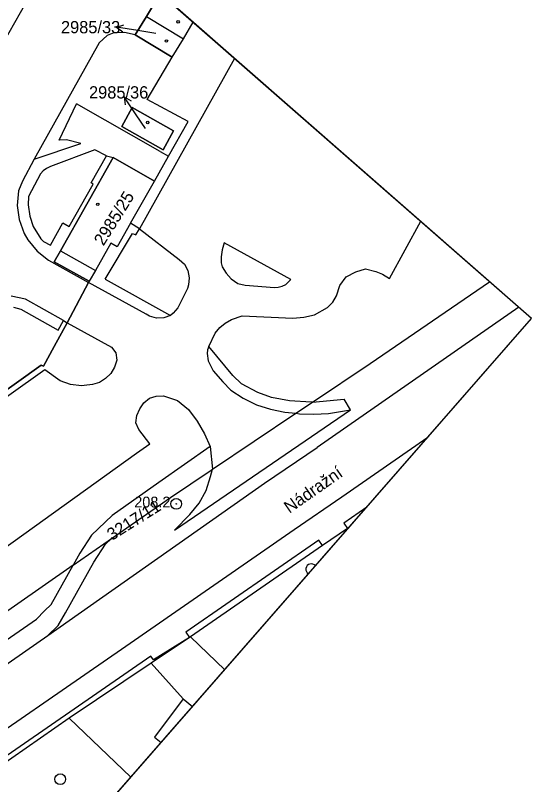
# Model space of a CAD drawing. Extents: x -620475 to -619963, y -1123010 to -1122510.
# Drawn here: x -620034.5 to -619962.9, y -1122851.2 to -1122744.6 of the extents above; entities that cross this region are included whole.
import ezdxf

# ---------------------------------------------------------------- set-up
doc = ezdxf.new("R2010")
doc.units = 0
for name, color, linetype in [('Hranice parcel', 7, 'Continuous'), ('Parcelní čísla', 7, 'Continuous'), ('Pop  PČ popisy', 7, 'Continuous'), ('Rámečky', 7, 'Continuous'), ('Rámečky-tisk', 7, 'Continuous'), ('Vnitřní kresba', 7, 'Continuous'), ('Věcná břemena k části', 7, 'Continuous'), ('Značky bodu BP', 7, 'Continuous'), ('Značky budov', 7, 'Continuous'), ('Značky kultur', 7, 'Continuous')]:
    doc.layers.add(name, color=color, linetype=linetype)

msp = doc.modelspace()

# ---------------------------------------------------------------- linework, layer by layer
at = {"layer": 'Hranice parcel'}
for p, q in [((-620014.82, -1122742.21), (-620016.36, -1122744.78)), ((-620016.36, -1122744.78), (-620011.23, -1122747.87)), ((-620011.23, -1122747.87), (-620009.85, -1122745.57)), ((-620012.77, -1122750.41), (-620011.23, -1122747.87)), ((-620018.54, -1122773.42), (-620015.21, -1122767.58)), ((-620007.52, -1122804.34), (-620007.17, -1122807.47)), ((-620026.52, -1122820.79), (-620021.18, -1122817.07)), ((-620010.26, -1122830.7), (-620005.5, -1122835.25)), ((-620015.7, -1122834.36), (-620027.05, -1122841.96)), ((-620027.05, -1122841.96), (-620041.07, -1122851.68)), ((-620027.05, -1122841.96), (-620018.53, -1122850.14))]:
    msp.add_line(p, q, dxfattribs=at)
for points in [[(-620027.34, -1122787.19), (-620029.12, -1122790.47), (-620030.63, -1122793.23), (-620030.93, -1122793.08), (-620062.93, -1122815.9), (-620079.47, -1122827.69), (-620107.97, -1122811.15), (-620126.88, -1122800.18), (-620134.93, -1122794.41), (-620148.77, -1122775.1), (-620158.3, -1122761.8), (-620160.13, -1122754.62), (-620158.82, -1122744.94), (-620155.87, -1122738.11), (-620144.37, -1122714.62)], [(-620016.36, -1122744.78), (-620017.89, -1122747.34), (-620012.77, -1122750.41)], [(-620004.12, -1122750.58), (-620017.33, -1122774.17), (-620018.54, -1122773.42)], [(-620015.21, -1122767.58), (-620013.28, -1122764.14), (-620010.56, -1122759.32), (-620016.25, -1122756.27), (-620012.77, -1122750.41)], [(-620019.78, -1122760.01), (-620014.04, -1122763.25), (-620012.58, -1122760.64), (-620018.31, -1122757.41), (-620019.78, -1122760.01)], [(-620015.21, -1122767.58), (-620020.97, -1122764.3), (-620028.26, -1122777.23), (-620029.12, -1122778.75), (-620024.29, -1122781.46)], [(-620018.54, -1122773.42), (-620020.4, -1122776.68), (-620021.28, -1122776.18), (-620023.43, -1122779.95), (-620024.29, -1122781.46)], [(-619993.34, -1122798.19), (-619993.51, -1122798.21), (-619996.52, -1122797.99), (-619999.01, -1122797.54), (-620000.91, -1122796.86), (-620003.16, -1122795.65), (-620004.39, -1122794.52), (-620007.71, -1122790.48), (-620006.81, -1122788.65), (-620006.19, -1122787.87), (-620005.43, -1122787.26), (-620004.57, -1122786.74), (-620003.06, -1122786.26), (-619996.05, -1122786.56), (-619994.54, -1122786.44), (-619993.04, -1122786.08), (-619991.26, -1122785.1), (-619990.52, -1122784.36), (-619990, -1122783.48), (-619989.53, -1122782.06), (-619988.65, -1122780.83), (-619987.32, -1122780.16), (-619985.99, -1122779.75), (-619984.54, -1122780.1), (-619983.61, -1122780.49), (-619982.64, -1122781.05), (-619978.32, -1122773.15)], [(-620024.29, -1122781.46), (-620024.38, -1122781.64), (-620027.34, -1122787.19)], [(-619993.34, -1122798.19), (-619985.33, -1122792.82), (-619968.77, -1122781.51)], [(-620027.34, -1122787.19), (-620021.21, -1122790.6), (-620020.57, -1122791.37), (-620020.47, -1122792.38), (-620020.76, -1122793.34), (-620021.28, -1122794.22), (-620022.02, -1122794.92), (-620022.87, -1122795.46), (-620023.84, -1122795.75), (-620024.96, -1122795.87), (-620025.37, -1122795.91), (-620026.87, -1122795.75), (-620028.3, -1122795.22), (-620030.44, -1122793.73), (-620056.1, -1122811.95)], [(-620043.43, -1122823.66), (-620017.73, -1122805.26), (-620015.89, -1122803.95), (-620017.39, -1122801.99), (-620017.8, -1122801.06), (-620017.7, -1122800.06), (-620017.25, -1122799.14), (-620016.69, -1122798.31), (-620015.92, -1122797.65), (-620014.98, -1122797.35), (-620013.97, -1122797.33), (-620012.05, -1122797.95), (-620010.5, -1122799.22), (-620009.31, -1122800.82), (-620008.3, -1122802.58), (-620007.52, -1122804.34)], [(-620007.17, -1122807.47), (-619995.65, -1122799.74), (-619993.34, -1122798.19)], [(-619977.35, -1122803.07), (-619989.26, -1122811.36), (-619995.85, -1122815.89), (-620011.68, -1122826.8), (-620019.22, -1122832.01), (-620044.54, -1122849.47), (-620064.79, -1122863.44), (-620079.86, -1122873.87), (-620081.95, -1122879.05), (-620081.71, -1122879.39)], [(-620007.52, -1122804.34), (-620014.61, -1122809.32), (-620021.11, -1122813.89), (-620023.96, -1122816.62), (-620025.58, -1122819.12), (-620026.52, -1122820.79)], [(-620021.18, -1122817.07), (-620013.01, -1122811.39), (-620007.39, -1122807.62), (-620007.17, -1122807.47)], [(-619988.22, -1122815.49), (-619988.48, -1122815.67), (-619991.93, -1122818.06), (-620010.26, -1122830.7)], [(-620074.02, -1122848.16), (-620069.41, -1122850.86), (-620061.9, -1122850.43), (-620053.99, -1122846.97), (-620049.77, -1122844.23), (-620030.04, -1122830.5), (-620028.57, -1122829.11), (-620027.57, -1122827.35), (-620023.65, -1122820.37), (-620022.03, -1122817.87), (-620021.18, -1122817.07)], [(-620026.52, -1122820.79), (-620038.5, -1122829.12), (-620047.37, -1122835.25), (-620060.13, -1122844.05), (-620068.97, -1122845.62), (-620069.79, -1122845.77)], [(-620010.26, -1122830.7), (-620010.39, -1122830.79), (-620015.7, -1122834.36)], [(-620015.7, -1122834.36), (-620011.24, -1122839.29), (-620015.25, -1122844.59), (-620014.33, -1122845.34)]]:
    msp.add_lwpolyline(points, dxfattribs=at)
at = {"layer": 'Pop  PČ popisy'}
for p, q in [((-620020.52, -1122746.27), (-620019.46, -1122745.93)), ((-620017.56, -1122746.74), (-620020.52, -1122746.27)), ((-620020.52, -1122746.27), (-620019.61, -1122746.92)), ((-620015.05, -1122747.14), (-620017.56, -1122746.74)), ((-620017.77, -1122758.39), (-620019.45, -1122755.9)), ((-620019.45, -1122755.9), (-620018.47, -1122756.45)), ((-620019.45, -1122755.9), (-620019.3, -1122757.01)), ((-620016.47, -1122760.3), (-620017.77, -1122758.39))]:
    msp.add_line(p, q, dxfattribs=at)
at = {"layer": 'Rámečky'}
for p, q in [((-619962.95, -1122786.6), (-620279.07, -1122510.07)), ((-620158.49, -1123010.14), (-619962.95, -1122786.6))]:
    msp.add_line(p, q, dxfattribs=at)
at = {"layer": 'Rámečky-tisk'}
msp.add_lwpolyline([(-620158.49, -1123010.14), (-619962.95, -1122786.6), (-620279.07, -1122510.07)], dxfattribs=at)
at = {"layer": 'Vnitřní kresba'}
for p, q in [((-620041.55, -1122757.64), (-620033.04, -1122742.83)), ((-620021.79, -1122747.41), (-620022.92, -1122748.42)), ((-620020.88, -1122747.04), (-620021.79, -1122747.41)), ((-620019.38, -1122747), (-620020.88, -1122747.04)), ((-620017.89, -1122747.34), (-620019.38, -1122747)), ((-620022.92, -1122748.42), (-620031.91, -1122764.55)), ((-620028.43, -1122761.89), (-620026.05, -1122756.86)), ((-620014.44, -1122763.48), (-620026.05, -1122756.86)), ((-620027.41, -1122761.88), (-620028.43, -1122761.89)), ((-620025.43, -1122762.36), (-620027.41, -1122761.88)), ((-620031.91, -1122764.55), (-620025.43, -1122762.36)), ((-620023.51, -1122763.25), (-620029.67, -1122765.56)), ((-620021.87, -1122764.08), (-620023.51, -1122763.25)), ((-620024.01, -1122767.82), (-620021.87, -1122764.08)), ((-620021.87, -1122764.08), (-620020.97, -1122764.3)), ((-620014.44, -1122763.48), (-620013.28, -1122764.14)), ((-620031.91, -1122764.55), (-620033.55, -1122767.57)), ((-620031.05, -1122766.59), (-620032.68, -1122769.69)), ((-620030.66, -1122766.18), (-620031.05, -1122766.59)), ((-620030.22, -1122765.84), (-620030.66, -1122766.18)), ((-620029.67, -1122765.56), (-620030.22, -1122765.84)), ((-620033.55, -1122767.57), (-620034.07, -1122768.94)), ((-620027.07, -1122773.88), (-620023.72, -1122768.01)), ((-620023.72, -1122768.01), (-620024.01, -1122767.82)), ((-620034.07, -1122768.94), (-620034.29, -1122770.95)), ((-620032.68, -1122769.69), (-620032.73, -1122770.86)), ((-620032.73, -1122770.86), (-620032.52, -1122772.45)), ((-620034.29, -1122770.95), (-620033.98, -1122772.91)), ((-620033.98, -1122772.91), (-620033.32, -1122774.85)), ((-620032.52, -1122772.45), (-620032.06, -1122773.89)), ((-620032.06, -1122773.89), (-620030.97, -1122775.57)), ((-620029.65, -1122776.45), (-620027.94, -1122773.37)), ((-620027.94, -1122773.37), (-620027.07, -1122773.88)), ((-620033.32, -1122774.85), (-620032.78, -1122775.71)), ((-620022.06, -1122781.16), (-620018.29, -1122774.82)), ((-620018.29, -1122774.82), (-620017.82, -1122775.04)), ((-620017.82, -1122775.04), (-620017.33, -1122774.17)), ((-620017.33, -1122774.17), (-620011.79, -1122778.42)), ((-620032.78, -1122775.71), (-620031.51, -1122777.29)), ((-620030.97, -1122775.57), (-620030.6, -1122775.96)), ((-620030.6, -1122775.96), (-620029.65, -1122776.45)), ((-620005.57, -1122776.13), (-620005.85, -1122777.08)), ((-619996.33, -1122781.23), (-620005.57, -1122776.13)), ((-620028.26, -1122777.23), (-620023.43, -1122779.95)), ((-620005.85, -1122777.08), (-620006.01, -1122778.08)), ((-620031.51, -1122777.29), (-620029.92, -1122778.54)), ((-620006.01, -1122778.08), (-620005.98, -1122778.9)), ((-620029.92, -1122778.54), (-620024.38, -1122781.64)), ((-620011.79, -1122778.42), (-620011.09, -1122779.1)), ((-620011.09, -1122779.1), (-620010.6, -1122779.97)), ((-620005.98, -1122778.9), (-620005.86, -1122779.45)), ((-620010.6, -1122779.97), (-620010.42, -1122780.98)), ((-620005.86, -1122779.45), (-620005.28, -1122780.34)), ((-620005.28, -1122780.34), (-620004.59, -1122781.12)), ((-620022.06, -1122781.16), (-620013.03, -1122786.2)), ((-620010.42, -1122780.98), (-620010.5, -1122781.96)), ((-620004.59, -1122781.12), (-620003.7, -1122781.74)), ((-619997.02, -1122781.9), (-619996.33, -1122781.23)), ((-620016.38, -1122786.03), (-620024.38, -1122781.64)), ((-620010.64, -1122782.44), (-620011.99, -1122785.12)), ((-620010.5, -1122781.96), (-620010.64, -1122782.44)), ((-620003.7, -1122781.74), (-620002.66, -1122782)), ((-620002.66, -1122782), (-619998.58, -1122782.3)), ((-619998.58, -1122782.3), (-619998.07, -1122782.26)), ((-619998.07, -1122782.26), (-619997.52, -1122782.12)), ((-619997.52, -1122782.12), (-619997.02, -1122781.9)), ((-620033.11, -1122783.92), (-620035.08, -1122783.5)), ((-620027.85, -1122786.88), (-620033.11, -1122783.92)), ((-620034.76, -1122785.06), (-620033.77, -1122785.31)), ((-620033.77, -1122785.31), (-620028.59, -1122788.23)), ((-620011.99, -1122785.12), (-620012.63, -1122785.89)), ((-619964.74, -1122785.03), (-619992.67, -1122804.48)), ((-620015.91, -1122786.27), (-620016.38, -1122786.03)), ((-620014.97, -1122786.55), (-620015.91, -1122786.27)), ((-620013.96, -1122786.51), (-620014.97, -1122786.55)), ((-620013.03, -1122786.2), (-620013.96, -1122786.51)), ((-620012.63, -1122785.89), (-620013.03, -1122786.2)), ((-620028.59, -1122788.23), (-620027.85, -1122786.88)), ((-620027.85, -1122786.88), (-620027.34, -1122787.19)), ((-620007.9, -1122790.93), (-620007.92, -1122791.46)), ((-620007.71, -1122790.48), (-620007.9, -1122790.93)), ((-620007.92, -1122791.46), (-620007.77, -1122792.46)), ((-620007.77, -1122792.46), (-620007.09, -1122793.84)), ((-620007.09, -1122793.84), (-620005.78, -1122795.39)), ((-620005.78, -1122795.39), (-620004.64, -1122796.54)), ((-620004.64, -1122796.54), (-620002.93, -1122797.66)), ((-620002.93, -1122797.66), (-620001.11, -1122798.55)), ((-620001.11, -1122798.55), (-619999.17, -1122799.18)), ((-619993.34, -1122798.19), (-619988.95, -1122797.79)), ((-619988.07, -1122799.25), (-619988.95, -1122797.79)), ((-620012.45, -1122815.92), (-619988.07, -1122799.25)), ((-619999.17, -1122799.18), (-619997.16, -1122799.6)), ((-619997.16, -1122799.6), (-619995.65, -1122799.74)), ((-619991.09, -1122799.77), (-619988.07, -1122799.25)), ((-619995.65, -1122799.74), (-619995.15, -1122799.79)), ((-619995.15, -1122799.79), (-619993.12, -1122799.86)), ((-619993.12, -1122799.86), (-619991.09, -1122799.77)), ((-620000, -1122809.41), (-619992.67, -1122804.48)), ((-620007.48, -1122808.49), (-620007.17, -1122807.47)), ((-620008.06, -1122810.42), (-620007.48, -1122808.49)), ((-620030.04, -1122830.5), (-620000, -1122809.41)), ((-620009.06, -1122812.19), (-620008.06, -1122810.42)), ((-620010.31, -1122813.76), (-620009.06, -1122812.19)), ((-619985.8, -1122812.72), (-619988.99, -1122814.93)), ((-620012.45, -1122815.92), (-620010.31, -1122813.76)), ((-619988.99, -1122814.93), (-619988.48, -1122815.67)), ((-619992.45, -1122817.31), (-620010.9, -1122830.03)), ((-619991.93, -1122818.06), (-619992.45, -1122817.31)), ((-620029.57, -1122826.21), (-620026.52, -1122820.79)), ((-620030.46, -1122827.11), (-620029.57, -1122826.21)), ((-620031.61, -1122828.24), (-620030.46, -1122827.11)), ((-620051.34, -1122841.97), (-620031.61, -1122828.24)), ((-620010.9, -1122830.03), (-620010.39, -1122830.79)), ((-620010.39, -1122830.79), (-620015.39, -1122833.86)), ((-620015.73, -1122833.37), (-620081.95, -1122879.05)), ((-620015.39, -1122833.86), (-620015.73, -1122833.37)), ((-620011.24, -1122839.29), (-620009.96, -1122840.34))]:
    msp.add_line(p, q, dxfattribs=at)
at = {"layer": 'Věcná břemena k části'}
for points in [[(-620062.93, -1122815.9), (-620030.93, -1122793.08), (-620030.63, -1122793.23), (-620029.12, -1122790.47), (-620027.34, -1122787.19), (-620024.38, -1122781.64), (-620024.29, -1122781.46), (-620029.12, -1122778.75), (-620028.26, -1122777.23), (-620020.97, -1122764.3), (-620015.21, -1122767.58), (-620013.28, -1122764.14), (-620010.56, -1122759.32), (-620016.25, -1122756.27), (-620012.77, -1122750.41), (-620017.89, -1122747.34), (-620016.36, -1122744.78), (-620014.82, -1122742.21)], [(-620062.93, -1122815.9), (-620030.93, -1122793.08), (-620030.63, -1122793.23), (-620029.12, -1122790.47), (-620027.34, -1122787.19), (-620024.38, -1122781.64), (-620024.29, -1122781.46), (-620029.12, -1122778.75), (-620028.26, -1122777.23), (-620020.97, -1122764.3), (-620015.21, -1122767.58), (-620013.28, -1122764.14), (-620010.56, -1122759.32), (-620016.25, -1122756.27), (-620012.77, -1122750.41), (-620017.89, -1122747.34), (-620016.36, -1122744.78), (-620014.82, -1122742.21)], [(-620062.93, -1122815.9), (-620030.93, -1122793.08), (-620030.63, -1122793.23), (-620027.34, -1122787.19), (-620024.38, -1122781.64), (-620024.29, -1122781.46), (-620029.12, -1122778.75), (-620028.26, -1122777.23), (-620020.97, -1122764.3), (-620015.21, -1122767.58), (-620013.28, -1122764.14), (-620010.56, -1122759.32), (-620016.25, -1122756.27), (-620012.77, -1122750.41), (-620017.89, -1122747.34), (-620016.36, -1122744.78), (-620014.82, -1122742.21)], [(-620062.93, -1122815.9), (-620030.93, -1122793.08), (-620030.63, -1122793.23), (-620029.12, -1122790.47), (-620027.34, -1122787.19), (-620024.38, -1122781.64), (-620024.29, -1122781.46), (-620029.12, -1122778.75), (-620028.26, -1122777.23), (-620020.97, -1122764.3), (-620015.21, -1122767.58), (-620013.28, -1122764.14), (-620010.56, -1122759.32), (-620016.25, -1122756.27), (-620012.77, -1122750.41), (-620017.89, -1122747.34), (-620016.36, -1122744.78), (-620014.82, -1122742.21)], [(-620018.31, -1122757.41), (-620012.58, -1122760.64), (-620014.04, -1122763.25), (-620019.78, -1122760.01), (-620018.31, -1122757.41)], [(-620012.58, -1122760.64), (-620014.04, -1122763.25), (-620019.78, -1122760.01), (-620018.31, -1122757.41), (-620012.58, -1122760.64)], [(-620012.58, -1122760.64), (-620014.04, -1122763.25), (-620019.78, -1122760.01), (-620018.31, -1122757.41), (-620012.58, -1122760.64)], [(-620012.58, -1122760.64), (-620014.04, -1122763.25), (-620019.78, -1122760.01), (-620018.31, -1122757.41), (-620012.58, -1122760.64)]]:
    msp.add_lwpolyline(points, dxfattribs=at)
at = {"layer": 'Značky bodu BP'}
for radius in [0.75, 0.03]:
    msp.add_circle((-620012.22, -1122812.28), radius, dxfattribs=at)
at = {"layer": 'Značky budov'}
for centre in [(-620011.96, -1122745.52), (-620013.58, -1122748.18), (-620016.17, -1122759.47), (-620023.1, -1122770.8)]:
    msp.add_circle(centre, 0.175, dxfattribs=at)
at = {"layer": 'Značky kultur'}
msp.add_line((-619993.89, -1122821.97), (-619992.91, -1122820.86), dxfattribs=at)
msp.add_circle((-620028.3, -1122850.41), 0.75, dxfattribs=at)
msp.add_arc((-619993.49, -1122821.33), 0.75, 39.2648, 238.3794, dxfattribs=at)

# ---------------------------------------------------------------- texts
at = {"layer": 'Parcelní čísla'}
for s, p in [('2985/33', (-620028.2, -1122747.11)), ('2985/36', (-620024.31, -1122756.14))]:
    msp.add_text(s, height=1.7, dxfattribs=at).set_placement(p)
for s, rotation, p in [('2985/25', 58, (-620022.31, -1122776.65)), ('3217/11', 32, (-620021.15, -1122817.43))]:
    msp.add_text(s, height=1.7, rotation=rotation, dxfattribs=at).set_placement(p)
at = {"layer": 'Pop  PČ popisy'}
msp.add_text('Nádražní', height=1.7, rotation=35, dxfattribs=at).set_placement((-619996.53, -1122813.66))
at = {"layer": 'Značky bodu BP'}
msp.add_text('208.2', height=1.5, dxfattribs=at).set_placement((-620018.04, -1122812.78))

doc.saveas('drawing.dxf')
